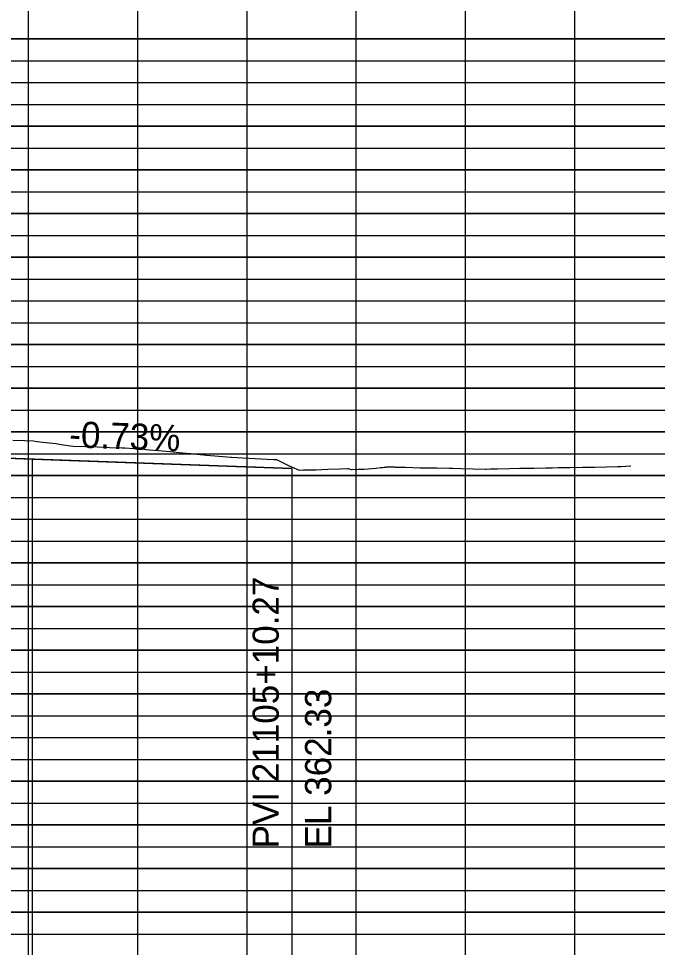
# Model space of a CAD drawing. Extents: x 1195880 to 1289360, y 2059330 to 2086925.
# Drawn here: x 1197454.1 to 1197600.3, y 2059552.7 to 2059765.4 of the extents above; entities that cross this region are included whole.
import ezdxf

# ---------------------------------------------------------------- set-up
doc = ezdxf.new("R2010")
doc.units = 0
for name, color, linetype in [('Default', 7, 'Continuous'), ('Existing Ground PGL', 7, 'Continuous'), ('Grid', 7, 'Continuous'), ('Profile', 7, 'Continuous'), ('Profile Annotation', 7, 'Continuous')]:
    doc.layers.add(name, color=color, linetype=linetype)

msp = doc.modelspace()

# ---------------------------------------------------------------- linework, layer by layer
for p in [(1197367.71, 2059667.81), (1197367.71, 2059667.81), (1197367.71, 2059667.81), (1197409.02, 2059666.3), (1197412.2, 2059666.18), (1197412.71, 2059666.17), (1197415.21, 2059666.07), (1197415.21, 2059666.07), (1197415.21, 2059666.07), (1197415.21, 2059666.07), (1197417.71, 2059665.98), (1197417.71, 2059665.98), (1197428.21, 2059665.6), (1197430.21, 2059665.53), (1197432.71, 2059665.44), (1197435.21, 2059665.34), (1197437.71, 2059665.25), (1197439.21, 2059665.2), (1197440.21, 2059665.16), (1197442.71, 2059665.07)]:
    msp.add_line(p, (1197516.64, 2059662.37))
at = {"layer": 'Default'}
for p, q in [((1197516.64, 2059662.37), (1197260.22, 2059671.73)), ((1197457.27, 2059340.74), (1197457.27, 2059664.54)), ((1197516.64, 2059662.37), (1197516.64, 2059340.74))]:
    msp.add_line(p, q, dxfattribs=at)
at = {"layer": 'Existing Ground PGL'}
msp.add_lwpolyline([(1197452.73, 2059668.86), (1197455.5, 2059668.75), (1197457.4, 2059668.69), (1197458.28, 2059668.58), (1197461.05, 2059668.25), (1197462.72, 2059668.06), (1197463.83, 2059667.88), (1197465.99, 2059667.55), (1197466.6, 2059667.52), (1197469.37, 2059667.4), (1197472.15, 2059667.3), (1197474.92, 2059667.21), (1197477.7, 2059667.13), (1197478.41, 2059667.11), (1197480.47, 2059666.98), (1197482.2, 2059666.87), (1197483.25, 2059666.75), (1197483.95, 2059666.68), (1197486.02, 2059666.49), (1197486.92, 2059666.42), (1197488.79, 2059666.23), (1197491.57, 2059665.96), (1197494.34, 2059665.7), (1197494.92, 2059665.65), (1197497.12, 2059665.44), (1197499.89, 2059665.19), (1197502.66, 2059664.96), (1197502.81, 2059664.94), (1197505.44, 2059664.78), (1197508.21, 2059664.63), (1197510.99, 2059664.49), (1197512.54, 2059664.42), (1197512.68, 2059664.41), (1197512.76, 2059664.4), (1197513.1, 2059664.41), (1197513.27, 2059664.38), (1197513.76, 2059664.11), (1197516.19, 2059662.93), (1197516.53, 2059662.77), (1197518.28, 2059662.01), (1197519.31, 2059662.03), (1197520.85, 2059662.05), (1197522.08, 2059662.1), (1197524.86, 2059662.21), (1197527.63, 2059662.3), (1197529.32, 2059662.36), (1197529.55, 2059662.37), (1197530.17, 2059662.14), (1197530.25, 2059662.14), (1197530.31, 2059662.14), (1197530.41, 2059662.14), (1197531.8, 2059662.22), (1197533.13, 2059662.18), (1197533.18, 2059662.19), (1197535.87, 2059662.45), (1197535.95, 2059662.46), (1197536.91, 2059662.57), (1197537.44, 2059662.63), (1197537.76, 2059662.67), (1197537.98, 2059662.69), (1197538.13, 2059662.71), (1197538.25, 2059662.72), (1197538.73, 2059662.72), (1197540.12, 2059662.72), (1197540.29, 2059662.71), (1197540.51, 2059662.69), (1197540.86, 2059662.68), (1197541.45, 2059662.67), (1197541.5, 2059662.67), (1197542.61, 2059662.65), (1197544.28, 2059662.6), (1197545.98, 2059662.54), (1197546.31, 2059662.54), (1197546.59, 2059662.53), (1197546.78, 2059662.53), (1197547.05, 2059662.52), (1197549.82, 2059662.49), (1197552.6, 2059662.44), (1197553.39, 2059662.43), (1197555.37, 2059662.39), (1197558.15, 2059662.32), (1197560.92, 2059662.25), (1197561.19, 2059662.25), (1197562.08, 2059662.28), (1197562.68, 2059662.29), (1197563.7, 2059662.31), (1197566.47, 2059662.38), (1197568.84, 2059662.44), (1197569.24, 2059662.44), (1197572.02, 2059662.48), (1197574.79, 2059662.52), (1197576.24, 2059662.55), (1197577.57, 2059662.57), (1197578.85, 2059662.59), (1197580.34, 2059662.61), (1197583.11, 2059662.66), (1197585.89, 2059662.71), (1197588.66, 2059662.77), (1197591.19, 2059662.82), (1197591.44, 2059662.83), (1197592.01, 2059662.85), (1197593.07, 2059662.91), (1197594.21, 2059662.97)], dxfattribs=at)
at = {"layer": 'Grid'}
for p, q in [((1197456.37, 2059350.74), (1197456.37, 2059950.74)), ((1197481.37, 2059350.74), (1197481.37, 2059950.74)), ((1197506.37, 2059350.74), (1197506.37, 2059950.74)), ((1197531.37, 2059350.74), (1197531.37, 2059950.74)), ((1197556.37, 2059350.74), (1197556.37, 2059950.74)), ((1197581.37, 2059350.74), (1197581.37, 2059950.74)), ((1197006.37, 2059760.74), (1198006.37, 2059760.74)), ((1198006.37, 2059760.74), (1197006.37, 2059760.74)), ((1197006.37, 2059755.74), (1198006.37, 2059755.74)), ((1197006.37, 2059750.74), (1198006.37, 2059750.74)), ((1197006.37, 2059745.74), (1198006.37, 2059745.74)), ((1197006.37, 2059740.74), (1198006.37, 2059740.74)), ((1198006.37, 2059740.74), (1197006.37, 2059740.74)), ((1197006.37, 2059735.74), (1198006.37, 2059735.74)), ((1197006.37, 2059730.74), (1198006.37, 2059730.74)), ((1198006.37, 2059730.74), (1197006.37, 2059730.74)), ((1197006.37, 2059725.74), (1198006.37, 2059725.74)), ((1197006.37, 2059720.74), (1198006.37, 2059720.74)), ((1198006.37, 2059720.74), (1197006.37, 2059720.74)), ((1197006.37, 2059715.74), (1198006.37, 2059715.74)), ((1197006.37, 2059710.74), (1198006.37, 2059710.74)), ((1198006.37, 2059710.74), (1197006.37, 2059710.74)), ((1197006.37, 2059705.74), (1198006.37, 2059705.74)), ((1197006.37, 2059700.74), (1198006.37, 2059700.74)), ((1197006.37, 2059695.74), (1198006.37, 2059695.74)), ((1197006.37, 2059690.74), (1198006.37, 2059690.74)), ((1198006.37, 2059690.74), (1197006.37, 2059690.74)), ((1197006.37, 2059685.74), (1198006.37, 2059685.74)), ((1197006.37, 2059680.74), (1198006.37, 2059680.74)), ((1198006.37, 2059680.74), (1197006.37, 2059680.74)), ((1197006.37, 2059675.74), (1198006.37, 2059675.74)), ((1197006.37, 2059670.74), (1198006.37, 2059670.74)), ((1198006.37, 2059670.74), (1197006.37, 2059670.74)), ((1197006.37, 2059665.74), (1198006.37, 2059665.74)), ((1197006.37, 2059660.74), (1198006.37, 2059660.74)), ((1198006.37, 2059660.74), (1197006.37, 2059660.74)), ((1197006.37, 2059655.74), (1198006.37, 2059655.74)), ((1197006.37, 2059650.74), (1198006.37, 2059650.74)), ((1197006.37, 2059645.74), (1198006.37, 2059645.74)), ((1197006.37, 2059640.74), (1198006.37, 2059640.74)), ((1198006.37, 2059640.74), (1197006.37, 2059640.74)), ((1197006.37, 2059635.74), (1198006.37, 2059635.74)), ((1197006.37, 2059630.74), (1198006.37, 2059630.74)), ((1198006.37, 2059630.74), (1197006.37, 2059630.74)), ((1197006.37, 2059625.74), (1198006.37, 2059625.74)), ((1197006.37, 2059620.74), (1198006.37, 2059620.74)), ((1198006.37, 2059620.74), (1197006.37, 2059620.74)), ((1197006.37, 2059615.74), (1198006.37, 2059615.74)), ((1197006.37, 2059610.74), (1198006.37, 2059610.74)), ((1198006.37, 2059610.74), (1197006.37, 2059610.74)), ((1197006.37, 2059605.74), (1198006.37, 2059605.74)), ((1197006.37, 2059600.74), (1198006.37, 2059600.74)), ((1197006.37, 2059595.74), (1198006.37, 2059595.74)), ((1197006.37, 2059590.74), (1198006.37, 2059590.74)), ((1198006.37, 2059590.74), (1197006.37, 2059590.74)), ((1197006.37, 2059585.74), (1198006.37, 2059585.74)), ((1197006.37, 2059580.74), (1198006.37, 2059580.74)), ((1198006.37, 2059580.74), (1197006.37, 2059580.74)), ((1197006.37, 2059575.74), (1198006.37, 2059575.74)), ((1197006.37, 2059570.74), (1198006.37, 2059570.74)), ((1198006.37, 2059570.74), (1197006.37, 2059570.74)), ((1197006.37, 2059565.74), (1198006.37, 2059565.74)), ((1197006.37, 2059560.74), (1198006.37, 2059560.74)), ((1198006.37, 2059560.74), (1197006.37, 2059560.74)), ((1197006.37, 2059555.74), (1198006.37, 2059555.74))]:
    msp.add_line(p, q, dxfattribs=at)
at = {"layer": 'Profile'}
for p, q in [((1197442.71, 2059665.07), (1197457.27, 2059664.54)), ((1197457.27, 2059664.54), (1197516.64, 2059662.37))]:
    msp.add_line(p, q, dxfattribs=at)
at = {"layer": 'Profile Annotation'}
msp.add_line((1197516.64, 2059662.37), (1197516.64, 2059562.37), dxfattribs=at)

# ---------------------------------------------------------------- texts
for s, rotation, p in [('-0.73%', 357.9096, (1197465.6, 2059667.24)), ('PVI 21105+10.27', 90, (1197513.64, 2059575.37)), ('EL 362.33', 90, (1197525.64, 2059575.37))]:
    msp.add_text(s, height=6, rotation=rotation, dxfattribs=at).set_placement(p)

doc.saveas('drawing.dxf')
